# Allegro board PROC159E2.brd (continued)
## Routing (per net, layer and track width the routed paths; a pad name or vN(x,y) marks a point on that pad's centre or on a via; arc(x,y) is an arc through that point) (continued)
SOC_OSPI0_D1: length 17.1
  L03_SIG1 w0.091: v1(47.44,39.67) 47.44,40.01 47.18,40.27 46.82,40.27 46.03,39.48 45.92,39.48 45.84,39.56 45.84,39.67 46.23,40.07 46.23,40.18 46.15,40.26 46.04,40.26 45.64,39.87 45.53,39.87 45.45,39.95 45.45,40.06 45.85,40.46 45.85,40.57 45.77,40.65 45.65,40.65 45.26,40.26 45.14,40.26 45.06,40.34 45.06,40.45 45.46,40.85 45.46,40.99 45.38,41.07 44.97,41.07 44.89,41.16 44.89,41.27 44.97,41.35 45.38,41.35 45.57,41.54 45.57,42.21 45.22,42.55 45.22,43.14 44.97,43.39 44.24,43.39 v1(43.67,42.82)
  BOTTOM w0.147: R91.1 R122.1 47.8,38 48.01,38.22 48.01,39.09 v1(47.44,39.67) ; U80.4 v1(43.67,42.82)
SOC_OSPI0_D2: length 15.6
  L03_SIG1 w0.091: v1(48.51,40.83) 48.23,41.11 47.99,41.11 47.48,40.6 47.37,40.6 47.29,40.68 47.29,40.79 47.86,41.37 47.86,41.48 47.78,41.56 47.67,41.56 47.09,40.99 46.98,40.99 46.9,41.07 46.9,41.18 47.47,41.75 47.47,41.87 47.39,41.95 47.28,41.95 46.7,41.38 46.59,41.38 46.51,41.46 46.51,41.57 47.08,42.14 47.08,42.26 47,42.34 46.89,42.34 46.14,41.59 46.02,41.59 45.94,41.67 45.94,41.78 46.7,42.53 46.7,42.69 46.2,43.19 45.95,43.19 45.81,43.05 v1(45.81,42.8)
  BOTTOM w0.147: U80.5 45.33,42.32 v1(45.81,42.8) ; R92.1 v1(48.51,40.83)
SOC_OSPI0_D3: length 17.3
  L03_SIG1 w0.091: v1(43.67,41.82) 43.22,41.82 43.11,41.94 43.11,43.04 42.97,43.18 42.79,43.18 42.67,43.06 42.67,36.4 43.82,35.25 46.44,35.25 46.65,35.47 48.08,35.47 v1(48.51,35.04)
  BOTTOM w0.147: v1(48.51,35.04) 48.58,35.12 R93.1 ; U80.6 v1(43.67,41.82)
SOC_OSPI0_D4: length 10.8
  TOP w0.147: R94.1 48.88,39.08 47.16,39.08 46.9,38.82 46.9,38.27 46.77,38.14 46.59,38.14 46.46,38.27 46.46,39.18 46.33,39.31 46.15,39.31 46.02,39.18 46.02,38.14 45.89,38.01 45.71,38.01 45.58,38.14 45.58,38.91 45.34,39.14 45.15,39.14 v1(44.83,38.82)
  BOTTOM w0.147: v1(44.83,38.82) 44.33,39.32 U80.11
SOC_OSPI0_D5: length 8.8
  TOP w0.147: R95.1 48.91,41.39 47.64,41.39 47.52,41.26 47.52,40.86 47.39,40.73 47.2,40.73 47.07,40.86 47.07,41.26 46.94,41.39 46.22,41.39 v1(43.65,38.82)
  BOTTOM w0.147: U80.12 v1(43.65,38.82)
SOC_OSPI0_D6: length 10.1
  TOP w0.147: R96.1 48.91,40.25 46.71,40.25 46.58,40.12 46.58,39.82 46.45,39.7 46.26,39.7 46.13,39.82 46.13,40.12 46.01,40.25 45.61,40.25 44.32,38.95 44.32,38.34 v1(44.83,37.83)
  BOTTOM w0.147: U80.13 44.34,38.32 v1(44.83,37.83)
SOC_OSPI0_D7: length 10.1
  TOP w0.147: R97.1 48.91,42.53 46.88,42.53 43.89,39.54 43.58,39.54 43.2,39.16 43.2,38.29 v1(43.67,37.82)
  BOTTOM w0.147: U80.14 v1(43.67,37.82)
SOC_OSPI0_DQS: length 18.3
  L03_SIG1 w0.091: v1(48.51,38.54) 48.51,38.06 48.43,37.98 47.19,37.98 47.11,37.9 47.11,37.79 47.19,37.71 48.43,37.71 48.51,37.63 48.51,37.51 48.43,37.43 47.19,37.43 47.11,37.35 47.11,37.24 47.19,37.16 48.43,37.16 48.51,37.08 48.51,36.96 48.43,36.88 47.19,36.88 47.11,36.8 47.11,36.69 47.19,36.61 48.43,36.61 48.55,36.49 48.55,35.93 48.37,35.75 46.75,35.75 46.57,35.93 46.57,36.63 46.39,36.82 v1(44.67,36.82)
  BOTTOM w0.147: v1(44.67,36.82) 44.17,37.32 U80.15 ; R118.1 v1(48.51,38.54)
SOC_OSPI0_LBCLK: length 9.1
  L03_SIG1 w0.091: v1(43.67,36.82) 43.67,37.15 44,37.48 44.44,37.48 44.64,37.28 45.42,37.28 45.57,37.43 45.57,37.89 45.74,38.06 46.13,38.06 46.39,37.8 46.66,37.8 46.78,37.91 46.78,38.68 47.09,39 47.82,39 v1(48.51,39.69)
  BOTTOM w0.147: U80.16 v1(43.67,36.82) ; R117.1 v1(48.51,39.69)
SOC_SPI1_CLK: length 77.1
  TOP w0.147: R140.1 v1(60.2,51.73) ; v1(63.01,8.36) 62.55,8.36 61.91,9 R43.2 U8.4
  L08_SIG2 w0.091: v1(60.2,51.73) 61.86,53.39 63.67,53.39 64.94,52.12 66.63,52.12 67.17,51.58 67.17,51.06 67.85,50.38 68.6,50.38 69.6,49.38 71.12,49.38 72.47,48.02 72.47,47.2 75.67,44 75.67,43.11 76.17,42.62 76.17,38.95 76.89,38.22 76.89,35.56 77.97,34.49 77.97,31.17 78.43,30.71 78.43,30.12 80,28.54 80,28.04 80.42,27.62 80.42,26.66 78.79,25.03 78.79,20.85 78.37,20.44 78.37,18.83 74.31,14.76 69.14,14.76 66.75,12.37 66.75,10.07 66.64,9.97 63.82,7.15 62.86,7.15 62.61,7.4 62.61,7.95 v1(63.01,8.36)
SOC_SPI1_CS0: length 50.4
  TOP w0.147: v1(61.84,19.3) R46.2 U8.12
  L03_SIG1 w0.091: v1(59.37,52.7) 59.69,52.39 59.69,51.12 60.37,50.43 60.37,40.16 60.59,39.94 60.59,37.46 60.81,37.24 61.99,37.24 62.17,37.06 62.17,36.63 62.36,36.44 65.92,36.44 66.17,36.19 66.17,35.09 66.42,34.84 68.32,34.84 69.06,34.1 69.06,32.53 67.2,30.67 67.2,26.34 65.36,24.5 65.36,23.48 64.68,22.79 63.61,22.79 63.61,22.79 62.34,22.79 62.05,22.5 62.05,19.88 61.84,19.67 v1(61.84,19.3)
  BOTTOM w0.147: R144.1 60.21,50.88 59.69,51.4 59.69,52.38 v1(59.37,52.7)
SOC_SPI1_D0: length 59.5
  TOP w0.147: R44.2 65.95,12.07 66.51,12.63 v1(66.51,13.16) 64.18,13.16 63.86,12.85 U8.7
  L08_SIG2 w0.091: v1(66.51,13.16) 66.99,13.65 66.99,14.05 69.89,16.94 74.98,16.94 75.91,17.87 75.91,33.69 74.93,34.68 74.93,37.95 74.2,38.68 74.2,41.99 69.65,46.54 69.65,47.64 68.04,49.25 67.41,49.25 66.68,49.98 64.79,49.98 63.33,51.45 v1(63.33,52.31)
  BOTTOM w0.147: R141.1 62.73,50.88 63.33,51.49 v1(63.33,52.31)
SOC_SPI1_D1: length 37.7
  TOP w0.147: U1.D9 v1(59.38,44.83) ; U8.9 R45.2 v1(65.27,19.3)
  L08_SIG2 w0.091: v1(59.38,44.83) 59.64,44.57 59.64,44.53 59.79,44.39 59.79,40.43 60.15,40.07 60.15,40.07 60.6,39.62 67.54,39.62 67.78,39.38 67.78,32.52 67.15,31.89 67.15,26.84 66.42,26.11 66.42,23.72 64.73,22.03 64.73,19.85 v1(65.27,19.3)
SOC_TA_I2C2_SCL: length 35.8
  L03_SIG1 w0.091: v1(46.1,77.46) 46.94,78.3 46.94,93.13 50.29,96.49 61.06,96.49 v1(63.11,98.54)
  BOTTOM w0.147: R302.1 v1(63.11,98.54) ; R310.2 v1(46.1,77.46)
SOC_TA_I2C2_SDA: length 44.6
  L08_SIG2 w0.091: v1(65.15,98.54) 65.57,98.97 66.34,98.97 66.59,98.72 66.59,97.58 66.15,97.15 66.15,90.87 64.71,89.42 64.71,78.74 63.61,77.65 61.93,77.65 60.53,79.05 50.44,79.05 49.61,78.22 47.92,78.22 v1(45.97,76.26)
  BOTTOM w0.147: R311.2 v1(45.97,76.26) ; R304.1 v1(65.15,98.54)
SOC_TCK: length 36.1
  TOP w0.147: U1.B3 v1(54.58,46.43) ; U30.12 v1(36.06,61.09)
  L03_SIG1 w0.091: v1(54.58,46.43) 54.97,46.82 54.97,47.4 53.54,48.83 53.54,51.72 49.71,55.54 36.61,55.54 33.99,58.17 33.99,60.35 34.73,61.09 v1(36.06,61.09)
  BOTTOM w0.147: TP52.1 36.1,61.06 v1(36.06,61.09)
SOC_TDI: length 38.6
  TOP w0.147: v1(34.41,59.14) 33.76,59.79 U30.7 ; U1.C5 v1(56.18,45.63)
  L03_SIG1 w0.091: v1(56.18,45.63) 55.79,46.02 55.79,47.47 55.21,48.04 54.64,48.04 53.72,48.96 53.72,51.79 48.39,57.12 36.43,57.12 v1(34.41,59.14)
  BOTTOM w0.114: 56.58,47.49 56.58,46.03 v1(56.18,45.63)
  BOTTOM w0.147: 56.58,47.49 56.58,48.04 57.19,48.65 TP53.1
SOC_TDO: length 33.4
  TOP w0.147: U30.4 34.21,61.74 35.13,60.83 35.13,58.48 36.22,57.39 TP54.1 43.7,56.76 44.39,56.76 v1(45.09,56.05)
  L08_SIG2 w0.091: v1(45.09,56.05) 44.56,55.52 44.56,52.39 45,51.95 53.08,51.95 53.79,52.65 54.91,52.65 v1(55.37,52.2)
  BOTTOM w0.147: v1(55.37,52.2) R177.1
SOC_TDO_R: length 5.5
  TOP w0.147: U1.C4 v1(55.38,45.63)
  BOTTOM w0.114: 54.98,47.49 54.98,46.03
  BOTTOM w0.147: 54.98,46.03 v1(55.38,45.63) ; R177.2 55.37,49.69 54.98,49.31 54.98,47.49
SOC_TMS: length 33.1
  TOP w0.147: U1.D5 v1(56.18,44.83) ; v1(36.06,59.14) U30.9
  L03_SIG1 w0.091: v1(56.18,44.83) 56.57,45.22 56.57,47.39 55.66,48.3 54.64,48.3 53.91,49.04 53.91,51.87 48.3,57.47 37.73,57.47 v1(36.06,59.14)
  BOTTOM w0.147: v1(36.06,59.14) 36.18,59.02 TP55.1
SOC_XDS_I2C2_SCL: length 20.9
  TOP w0.147: R312.2 v1(39.03,78.27)
  L03_SIG1 w0.091: v1(27.68,88.72) 28.66,87.74 34.63,87.74 38.17,84.21 38.17,79.14 v1(39.03,78.27)
  BOTTOM w0.147: U52.82 27.94,88.46 v1(27.68,88.72)
SOC_XDS_I2C2_SDA: length 22.6
  TOP w0.147: R313.2 v1(39.11,76.06)
  L03_SIG1 w0.091: v1(39.11,76.06) 39.46,76.41 39.46,78.76 38.35,79.87 38.35,84.29 34.71,87.93 29.36,87.93 v1(28.57,88.72)
  BOTTOM w0.147: v1(28.57,88.72) 28.34,88.49 U52.81
SPI1_MUX_OE#: length 2
  TOP w0.147: U8.15 60.61,18.84 61.08,19.3 R50.1
SPI1_MUX_SEL: length 146.3
  TOP w0.147: v1(60.83,9.92) R49.1 U8.1
  L08_SIG2 w0.091: v1(57.88,65.65) 57.51,65.65 56.96,66.2 56.96,66.75 55.97,67.73 54.89,67.73 53.74,68.88 53.74,69.34 53,70.08 49.81,70.08 47.82,68.09 45.44,68.09 45.21,67.87 30.11,67.87 28.19,65.94 26.48,65.94 19.92,59.39 19.92,58.06 15.32,53.46 15.32,39.14 17.39,37.06 17.39,33.88 15.35,31.84 15.35,22.05 18.39,19.02 v1(23.79,19.02)
  BOTTOM w0.147: v1(57.88,65.65) 57.56,65.97 57.27,65.97 56.96,66.29 U60.11 ; v1(23.79,19.02) 24.11,19.34 24.51,19.34 24.52,19.34 25.68,20.51 35.52,20.51 36.85,21.83 49.55,21.83 52.82,18.56 56.48,18.56 60.07,14.98 60.07,10.68 v1(60.83,9.92)
SW_PB_INTN: length 12.2
  TOP w0.147: Q10.2 59.62,94.18 59.65,94.2 v1(59.65,95.49) SW11.2
  BOTTOM w0.147: U76.3 52.56,92.43 52.96,92.84 56.14,92.84 58.8,95.49 v1(59.65,95.49)
SW_PB_PORZ: length 5.9
  TOP w0.147: SW10.2 52.69,95.79 53.15,95.33 Q9.2 v1(53.15,92.38)
  BOTTOM w0.147: v1(53.15,92.38) 53.56,91.97 U76.1
SW_PB_RESETZ: length 28
  TOP w0.147: Q11.2 SW12.2 65.18,96.84 64.64,97.37 64.64,98.9 63.91,99.63 51.8,99.63 50.42,98.25 50.42,95.61 52.07,93.96 v1(52.07,93.33)
  BOTTOM w0.147: U76.6 52.56,93.82 v1(52.07,93.33)
SYS_BOOTMODE0: length 8.6
  TOP w0.147: R323.2 SW6.1 v1(62.86,84.71) 61.97,83.81 U47.2
  BOTTOM w0.147: U48.6 63.77,86.3 63.53,86.06 63.53,85.38 v1(62.86,84.71)
SYS_BOOTMODE1: length 9.3
  TOP w0.147: U47.3 61.47,84.57 v1(62.86,85.97) 63.17,85.97 63.18,85.98 SW6.2 R324.2
  BOTTOM w0.147: v1(62.86,85.97) 63.59,86.7 U48.7
SYS_BOOTMODE2: length 10.5
  TOP w0.147: U47.4 60.97,84.95 62.23,86.21 62.23,86.61 v1(62.86,87.25) SW6.3 R325.2
  BOTTOM w0.147: U48.8 63.46,87.1 63.31,87.25 v1(62.86,87.25)
SYS_BOOTMODE3: length 14.2
  TOP w0.147: U47.5 60.27,81.91 60.25,81.93 60.25,85.9 v1(62.86,88.52) SW6.4 R326.2
  BOTTOM w0.147: v1(62.86,88.52) 64.37,88.52 64.95,87.94 U48.9
SYSBOOT_BUF_ENZ: length 6.7
  BOTTOM w0.147: U49.2 67.93,96.48 67.44,96 66.04,96 64.8,94.77 R328.1
TA_GPIO1: length 33.2
  TOP w0.147: R371.2 v1(45.59,105.27) ; Q10.1 61.55,95.15 60.63,96.08 60.63,98.87 60.32,99.17 59.52,99.17 v1(58.84,98.49)
  L08_SIG2 w0.091: v1(58.84,98.49) 59.22,98.11 60.24,98.11 60.49,98.36 60.49,98.74 56.62,102.61 44.64,102.61 44.19,103.06 44.19,103.87 v1(45.59,105.27)
  BOTTOM w0.147: R298.1 v1(58.84,98.49) 58.84,97.89 58.92,97.81 R291.1
TA_GPIO1_XDS: length 22.4
  TOP w0.147: U57.2 R365.2 31.57,105.9 v1(31.56,105.9)
  L08_SIG2 w0.091: v1(31.14,88.72) 31.41,88.98 31.41,89.23 32.55,90.36 32.55,102.99 31.14,104.4 31.14,105.48 v1(31.56,105.9)
  BOTTOM w0.147: U52.74 v1(31.14,88.72)
TA_GPIO2: length 74.7
  L08_SIG2 w0.091: v1(60.07,98.54) 56.3,102.31 45.71,102.31 44.45,101.05 44.45,98.08 45.51,97.02 45.51,74.26 42.89,71.65 28.71,71.65 27.81,72.56 v1(19.81,72.56)
  BOTTOM w0.147: R290.1 v1(60.07,98.54) R299.1 ; R378.2 v1(19.81,72.56)
TA_GPIO2_XDS: length 19.5
  L08_SIG2 w0.091: v1(31.54,86.1) 31.54,85.52 27.55,81.52 18.3,81.52 v1(17.92,81.14)
  BOTTOM w0.147: U58.2 R377.2 v1(17.92,81.14) ; U52.73 v1(31.54,86.1)
TA_GPIO3: length 43.8
  TOP w0.147: R372.2 v1(45.59,104.13)
  L03_SIG1 w0.091: v1(61.08,98.54) 64.26,101.71 J12.1
  L08_SIG2 w0.091: J12.1 59.82,101.71 57.4,104.13 v1(45.59,104.13)
  BOTTOM w0.147: J12.1 68.14,101.71 67.3,100.87 67.3,98.46 66.98,98.14 U49.1 ; R300.1 v1(61.08,98.54) 61.08,97.93 61.21,97.81 R289.1
TA_GPIO3_XDS: length 20.7
  TOP w0.147: v1(31.57,104.57) R366.2 U57.3
  L08_SIG2 w0.091: v1(31.57,104.57) 33.02,103.12 33.02,90.06 v1(32.65,89.69)
  BOTTOM w0.147: U52.72 31.94,88.83 32.33,89.22 32.33,89.37 v1(32.65,89.69)
TA_GPIO4: length 39.2
  TOP w0.147: R373.2 v1(44.87,103.45) ; U47.1 v1(62.47,83.03)
  L08_SIG2 w0.091: v1(44.87,103.45) 56.72,103.45 60.97,99.2 61.44,99.2 v1(62.1,98.54) 62.9,97.74 62.9,91.3 62.08,90.48 62.08,83.42 v1(62.47,83.03)
  BOTTOM w0.147: R301.1 v1(62.1,98.54) 62.1,98.08 62.35,97.83 R288.1
TA_GPIO4_XDS: length 21
  TOP w0.147: v1(35.8,102.72) U57.4 R367.2
  L08_SIG2 w0.091: v1(32.69,88.69) 33.62,89.62 33.62,100.54 v1(35.8,102.72)
  BOTTOM w0.147: v1(32.69,88.69) 32.34,88.34 U52.71
TA_PORZN: length 21.9
  TOP w0.147: R374.2 v1(44.87,100.87) ; v1(56.88,98.54) 56.38,98.04 56.38,95.58 55.05,94.24 Q9.1
  L08_SIG2 w0.091: v1(44.87,100.87) 45.93,101.93 53.49,101.93 v1(56.88,98.54)
  BOTTOM w0.147: R293.1 56.64,97.84 56.88,98.08 v1(56.88,98.54) R296.1
TA_PORZN_XDS: length 19.9
  TOP w0.147: v1(31.57,100.86) R368.2 U57.5
  L08_SIG2 w0.091: v1(31.57,100.86) 30.84,100.14 30.84,91.5 29.12,89.78 29.12,86.94 v1(29.94,86.12)
  BOTTOM w0.147: U52.77 v1(29.94,86.12)
TA_POWERDOWNZ: length 161.5
  TOP w0.147: R376.2 v1(44.87,98.33)
  L03_SIG1 w0.091: v1(104.07,98.36) 104.07,104.16 100.32,107.92 81.42,107.92 75.41,101.9 71.28,101.9 70.36,102.83 68.27,102.83 67.49,102.05 59.38,102.05 v1(55.88,98.54)
  L08_SIG2 w0.091: v1(104.07,98.36) 104.07,97.45 105.48,96.05 105.48,83.57 100.76,78.86 97.87,78.86 96.7,77.68 92.49,77.68 92.09,78.07 90.97,78.07 90.47,77.57 90.47,76.51 94.56,72.41 94.56,66.27 95.32,65.51 95.32,40.69 93.89,39.26 93.89,38.13 94.2,37.83 95.19,37.83 v1(95.72,37.31) ; v1(55.88,98.54) 55.23,99.18 46.49,99.18 45.63,98.33 v1(44.87,98.33)
  BOTTOM w0.147: Q12.1 87.47,36.93 87.71,37.17 91.05,37.17 91.66,37.78 95.24,37.78 v1(95.72,37.31) ; R295.1 v1(55.88,98.54) 55.41,98.07 R468.1
TA_POWERDOWNZ_XDS: length 14.2
  TOP w0.147: U57.7 R370.2 v1(31.57,98.32)
  L08_SIG2 w0.091: v1(31.57,98.32) 31.57,90.74 v1(29.54,88.72)
  BOTTOM w0.147: U52.78 v1(29.54,88.72)
TA_RESETZ: length 33.9
  TOP w0.147: v1(57.85,98.54) 58.38,98.01 58.38,91.13 58.76,90.75 61.7,90.75 63.58,92.64 Q11.1 ; R375.2 v1(44.87,99.6)
  L08_SIG2 w0.091: v1(44.87,99.6) 45.58,100.31 54.71,100.31 56.3,98.72 56.3,98.52 56.71,98.11 57.42,98.11 v1(57.85,98.54)
  BOTTOM w0.147: R297.1 v1(57.85,98.54) 57.85,98.08 57.78,98.02 R292.1
TA_RESETZ_XDS: length 15.5
  TOP w0.147: v1(31.57,99.59) R369.2 U57.6
  L08_SIG2 w0.091: v1(31.57,99.59) 31.99,99.17 31.99,90.53 v1(31.11,89.65)
  BOTTOM w0.147: U52.76 30.34,88.88 v1(31.11,89.65)
TCAN_WAKE: length 7.3
  TOP w0.147: U29.9 v1(19.9,24.41)
  BOTTOM w0.147: v1(19.9,24.41) 19.9,18.48 R31.2
TM4C129_RST#: length 7.6
  BOTTOM w0.147: U52.70 32.74,86.2 32.51,85.97 TP73.1 33.9,83.55 34.16,83.3 R353.2 R355.1
TM4C129_TCK: length 3.1
  BOTTOM w0.147: U52.100 19.19,90.11 18.71,90.59 TP68.1
TM4C129_TDI: length 5.5
  BOTTOM w0.147: TP70.1 16.67,89.31 U52.98
TM4C129_TDO: length 3.1
  BOTTOM w0.147: U52.97 19.2,88.91 18.74,88.46 TP71.1
TM4C129_TMS: length 5.4
  BOTTOM w0.147: TP69.1 16.6,89.71 U52.99
TMP411_ALERT: length 1.7
  BOTTOM w0.147: R160.2 U27.6
TMP411_THERM: length 1.8
  BOTTOM w0.147: U27.4 R161.2
TPS2121_CP2: length 6.7
  TOP w0.147: U4.3 96.02,19.81 v1(95.52,20.31)
  BOTTOM w0.147: R11.2 R15.1 97.59,20.87 97.02,20.31 v1(95.52,20.31)
TPS2121_OV1: length 5.4
  TOP w0.147: U4.5 95.02,19.81 v1(94.52,20.31)
  BOTTOM w0.147: v1(94.52,20.31) 94.52,21.1 95.05,21.64 R12.2 R16.1
TPS2121_OV2: length 8.8
  TOP w0.147: U4.4 v1(95.52,19.29)
  BOTTOM w0.147: R14.1 R10.2 100.13,20.45 98.97,19.29 v1(95.52,19.29)
TPS2121_PR1: length 5.2
  TOP w0.147: U4.6 v1(94.52,19.29)
  BOTTOM w0.147: R17.1 R13.2 93.78,20.03 v1(94.52,19.29)
TPS2296_EN: length 8.5
  TOP w0.147: U2.4 LD1.1 103.78,15.39 103.44,15.74 v1(101.47,15.74) ; U3.3 v1(103.25,18.55)
  BOTTOM w0.147: v1(101.47,15.74) 102.11,16.38 102.11,17.42 v1(103.25,18.55)
TUSB_OUT1: length 3.2
  TOP w0.147: U2.2 103.28,11.6 v1(103.03,11.35)
  BOTTOM w0.147: U17.7 102,11.67 R4.2 v1(103.03,11.35)
TUSB_OUT2: length 5.5
  TOP w0.147: v1(100.2,11.35) 102,11.35 102.78,12.13 U2.1
  BOTTOM w0.147: U17.8 101.6,11.86 101.08,11.35 R3.2 v1(100.2,11.35)
UART0_RXD: length 57.5
  TOP w0.147: U1.A7 v1(57.78,47.23)
  L03_SIG1 w0.091: v1(50.9,94.09) 50.9,92.62 55.63,87.89 55.63,77.83 57.74,75.72 57.74,72.97 56.29,71.51 54.58,71.51 51.33,68.27 51.33,58.08 56.26,53.16 56.26,50.6 57.17,49.69 57.17,47.84 v1(57.78,47.23)
  BOTTOM w0.147: R344.1 v1(50.9,94.09)
UART0_TXD: length 59.4
  TOP w0.147: U1.A6 v1(56.98,47.23)
  L03_SIG1 w0.091: v1(56.98,47.23) 56.98,47.6 56.21,48.38 56.21,49.67 56.05,49.82 56.05,53 51,58.05 51,70.21 52.57,71.78 56.06,71.78 57.46,73.17 57.46,75.62 55.35,77.73 55.35,87.76 50.54,92.57 50.54,93.15 49.98,93.71 v1(49.4,93.71)
  BOTTOM w0.147: U54.3 v1(49.4,93.71)
UART2_MUX_SEL: length 12.7
  TOP w0.147: v1(56.46,66.54) 55.92,67.07 51.08,67.07 50.69,66.68 R62.2 R67.1 46.34,66.68 45.87,66.21 U20.1
  BOTTOM w0.147: U60.12 v1(56.46,66.54)
UART2_RXD_HSEC: length 110.9
  TOP w0.147: J15.161 104.84,4.21 105.18,4.56 v1(105.64,4.56) ; U20.3 47.75,64.31 49.11,62.95 v1(49.11,62.16)
  L08_SIG2 w0.091: v1(105.64,4.56) 106.38,3.82 108.84,3.82 109.36,4.33 109.36,7.96 107.69,9.63 105.52,9.63 105.13,10.02 103.6,10.02 102.33,11.29 102.33,11.73 98.57,15.5 96.51,15.5 95,17.01 95,20.68 86.66,29.02 86.24,29.02 85.46,29.8 85.46,39.91 82.56,42.81 82.56,45.24 80.41,47.4 80.41,51.17 77.79,53.79 71.71,53.79 71.1,54.4 69.44,54.4 68.98,54.86 68.98,55.21 68.47,55.73 67.26,55.73 66.09,56.9 52.92,56.9 49.11,60.71 v1(49.11,62.16)
UART2_TXD_HSEC: length 110.4
  TOP w0.147: v1(47.41,62.09) 47.15,62.36 U20.6
  L08_SIG2 w0.091: v1(104.04,5.58) 103.66,5.58 103.07,6.17 103.07,6.59 101.52,8.14 99.14,8.14 98.74,8.55 98.74,9.06 92.44,15.36 87.97,15.36 83.19,20.15 83.19,27.87 79.54,31.52 79.54,38.82 77.94,40.42 77.94,48.6 76.68,49.86 74.93,49.86 73.31,51.48 70.92,51.48 69.89,52.52 67.95,52.52 67.19,53.28 66.19,53.28 65.03,54.44 53.98,54.44 51.72,52.18 45.26,52.18 44.82,52.62 44.82,55.05 45.67,55.89 45.67,60.35 v1(47.41,62.09)
  BOTTOM w0.147: v1(104.04,5.58) 104.67,4.94 104.67,4.27 104.84,4.1 J15.162
USB_XDS110_ID: length 20.7
  TOP w0.147: v1(15.11,93.97) 14.74,94.33 J13.4
  L08_SIG2 w0.091: v1(15.11,93.97) 22.47,86.6 v1(22.47,83.05)
  BOTTOM w0.147: R338.2 v1(22.47,83.05) ; U53.4 13.16,93.38 13.33,93.21 14.73,93.21 15.11,93.59 v1(15.11,93.97)
USD_LS_EN: length 2
  TOP w0.147: U23.3 14.06,53.84 14.06,53.84 U22.4
USER_LED0: length 10.5
  TOP w0.147: U20.5 47.35,63.01 48.01,62.35 48.01,61.58 49.81,59.79 53.55,59.79 53.88,59.46 R146.2
USER_LED1: length 19.2
  TOP w0.147: R147.2 47.93,55.15 46.07,53.29 46.07,52.7 44.02,50.65 44.02,45.75 45.97,43.8 49.04,43.8 R194.2
VLIN: length 9.6
  TOP w0.381: J10.1 D6.2 ; D6.2 C236.1 SW4.2 ; D6.2 U45.7
VMAIN: length 23.4
  TOP w0.381: TP80.1 97.66,88.45 v1(98.18,88.97) ; C12.2 97.34,16.94 U4.1 ; R137.1 58.64,63.47 57.73,62.56 57.73,57.8 57.19,57.27 R138.1 ; R433.1 v1(79.2,28.28)
  BOTTOM w0.254: U14.7 99.31,87.21 98.69,87.83
  BOTTOM w0.305: 53.94,79.39 53.94,79.21 53.58,78.85 ; 53.94,79.39 U10.2 ; 53.94,79.39 54.37,78.96
  BOTTOM w0.381: v1(53.97,28.18) 53.97,28.75 54.34,29.13 R201.1 ; U5.8 87.98,15.61 88.21,15.84 v1(90.42,15.84)
  vias: v1(53.97,77.58) v1(54.86,77.58) v1(90.42,17.77) v1(90.42,16.8) v1(91.44,17.77) v1(91.44,16.8)
VMAIN_12V0: length 10.3
  TOP w0.305: U29.10 18.03,23.91 17.69,24.25 C348.2
  TOP w0.381: C348.2 v1(17.07,23.54)
  BOTTOM w0.381: R21.2 C20.1 76.74,19.11 v1(76.85,19.22) ; v1(17.07,23.54) 17.07,21.21 16.85,20.99 R175.1
  vias: v1(93.39,28.66) v1(94.14,27.91)
VMAIN_MON: length 3
  TOP w0.381: U79.2 81.18,29.94 81.15,29.97 R434.1 R433.2
VMAINP_12V0:
  vias: v1(97.4,32.25) v1(97.4,31.36) v1(97.4,30.47) v1(98.42,32.25) v1(98.42,31.36) v1(98.42,30.47) v1(99.31,33.13) v1(99.31,32.25) v1(99.31,31.36) v1(99.31,30.47)
VPP_1V7: length 55.8
  TOP w0.381: R463.1 85.77,45.17 C346.1 84.59,46.22 TP76.1 ; R83.1 49.12,35.69 47.83,35.69 47.82,35.68 R63.1 47.69,35.11 v1(47.62,35.04)
  L05_PWR1 w0.305: v1(47.62,35.04) 48,34.66 48,34.26 50.46,31.8 67.63,31.8 68.71,30.71 71.56,30.71 72.2,31.36 78.16,31.36 84.64,37.84 84.64,44.61 TP76.1
VPP_LDO_EN: length 72.1
  TOP w0.147: v1(86.31,59.6) 84.99,59.6 84.42,59.03 84.42,59.03 84.42,54.45 80.46,50.49 80.46,46 82.64,43.82 83.73,43.82 85.09,42.46 90.14,42.46 91.47,43.79 R465.1 90.91,44.85 90.84,44.92 U66.4 ; v1(61.61,63.44) 62.52,64.36 62.52,66.52 63.28,67.28 74.34,67.28 74.84,66.78 74.84,66.32 75.36,65.8 78.32,65.8 80.84,63.28 v1(80.84,61.89)
  L08_SIG2 w0.091: v1(80.84,61.89) 84.02,61.89 v1(86.31,59.6)
  BOTTOM w0.147: v1(61.61,63.44) 60.65,64.4 57.66,64.4 55.96,66.1 U60.13
VPP_R: length 3.5
  TOP w0.305: U1.N3 v1(54.58,36.83)
  TOP w0.381: v1(51.32,36.67) 51.05,36.4 C101.1 50.39,35.98 R83.2 50.03,35.62 R467.2
VREG: length 2.1
  TOP w0.305: v1(101.7,46.03) 101.69,46.02 U7.40
  BOTTOM w0.381: C62.1 101.7,45.45 v1(101.7,46.03)
VREG_1P8_OUT: length 3.9
  TOP w0.305: U7.39 102.19,45.77 102.24,45.81 102.24,46.19 102.23,46.2 v1(102.23,46.73)
  BOTTOM w0.381: C61.1 103.19,45.15 102.36,45.97 102.36,46.53 102.32,46.57 102.32,46.64 v1(102.23,46.73)
VSYS_1V2: length 17.4
  TOP w0.254: 90.29,55.99 90.59,56.3 U9.3 90.58,56.75 90.55,56.72 90.13,56.72 89.78,56.38
  TOP w0.381: R52.1 90.58,61.08 v1(90.58,61.48) 91.72,62.62 TP82.1
  L06_PWR2 w0.305: v1(85.09,53.2) 85.59,53.71 87.67,53.71 90.58,56.62 v1(90.58,61.48)
  BOTTOM w0.381: R75.3 84.2,50.63 v1(84.2,51.42)
  vias: v1(83.31,52.31) v1(83.31,51.42) v1(84.2,53.2) v1(84.2,52.31) v1(85.09,54.09) v1(85.09,52.31) v1(85.09,51.42) v1(85.97,54.09) v1(85.97,53.2) v1(85.97,52.31)
VSYS_1V2_EN: length 4.8
  TOP w0.147: v1(93.14,56.3) 93.14,56.75 92.64,57.25 U9.5
  BOTTOM w0.147: v1(93.14,56.3) 93.14,55.36 92.99,55.21 R430.2 R51.2
VSYS_1V2_FB: length 2.8
  TOP w0.203: R56.2 R52.2 90.27,59.2 90.33,59.13 U9.9
VSYS_1V2_PG: length 98.8
  TOP w0.147: R76.2 58.71,77.13 67.1,77.13 v1(67.43,77.46) ; U9.1 89.82,57.75 89.63,57.94 89.63,59.21 89.06,59.78 R59.2 88.41,59.78 88.11,60.08 v1(88.11,61.41) 87.43,62.09 87.02,62.09 84.09,59.17 84.09,54.54 79.78,50.22 79.78,46.26 82.54,43.5 83.48,43.5 84.04,42.94 84.04,38.82 80.19,34.98 U78.1
  L08_SIG2 w0.091: v1(88.11,61.41) 88.11,59.42 86.43,57.73 79.14,57.73 77.44,56.04 72.21,56.04 71.72,55.55 71.16,55.55 70.58,56.13 70.58,56.47 69.71,57.34 67.48,57.34 67.1,57.72 67.1,68.4 67.28,68.58 67.28,76.94 67.43,77.09 v1(67.43,77.46)
VSYS_1V2_SW: length 1.7
  TOP w0.254: 89.04,57.25 U9.2
  TOP w0.381: 88.77,57.52 89.04,57.25
VSYS_1V7_FB: length 2.8
  TOP w0.147: R464.1 R463.2 86.99,44.96 87.6,45.57 U66.2
VSYS_3V3_LDO1: length 280.6
  TOP w0.203: U87.30 73.52,60.39 v1(73.02,59.89)
  TOP w0.254: 103,50.87 v1(103,51.79)
  TOP w0.305: v1(79.01,55.89) 79.01,56.09 78.71,56.39 U87.1 ; 102.87,47.61 102.87,46.6 ; 102.87,46.6 103.19,46.27 U7.37 ; 102.87,46.6 102.87,46.47 102.69,46.3 U7.38 ; U84.30 v1(89.06,88.85) ; v1(23.84,24.75) C175.2 23.2,23.99 23.12,23.91 U29.5 ; U85.17 93.83,105.84 94.14,106.14 v1(94.14,106.34) ; R1647.1 v1(25.55,25.62) ; U85.1 v1(94.14,97.84) ; U84.17 93.83,92.85 94.14,93.15 v1(94.14,93.35) ; v1(94.14,84.34) 94.14,84.59 93.88,84.85 U84.1 ; v1(79.01,64.39) U87.17 ; U85.30 v1(89.06,101.84)
  TOP w0.381: R153.1 v1(56.7,51.73) ; R153.1 R152.1 57.84,54.4 59.03,55.59 R3842.1 v1(59.83,56.45) ; R153.1 R157.1 R156.1 ; U42.4 v1(19.41,39.48) ; U42.1 18.98,42.52 C233.1 18.98,44.6 18.92,44.66 FL6.1 C230.1 v1(15.74,45.9) ; R46.1 v1(62.56,21.07) ; R425.1 v1(51.83,107.41) ; J15.119 67.84,4.79 67.18,5.45 67.18,8.12 65.95,9.34 v1(65.95,10.4) 65.91,10.45 R44.1 ; v1(81.3,106.34) 81.8,105.84 C373.1 ; R3852.2 v1(96.56,101.34) ; R1678.2 R1679.2 42.45,37.2 42.65,36.99 C3743.1 42.65,35.69 v1(42.68,35.66) ; v1(49.92,97.02) 49.92,95.92 48.29,94.29 R3858.1 ; R470.1 74.97,28.4 v1(74.45,27.88) ; R80.1 R78.2 99.21,82.43 96.53,79.75 v1(95.53,79.75) ; R45.1 v1(65.27,20.28) ; v1(96.23,87.51) 95.86,87.88 R3849.2 ; v1(52.76,66.55) 53.35,65.97 C86.1 U20.16 ; C178.1 v1(41.72,63.56) ; U19.E4 v1(30.35,45.16) ; v1(87.29,88.35) 86.63,89.01 C371.1 ; R59.1 89.02,61.41 v1(88.98,61.45) ; R108.2 v1(25.81,40.66) ; R263.2 v1(69.77,94.3) ; R429.1 v1(65.8,107.41) ; R200.1 94.07,42.89 v1(94.32,43.14) ; R85.1 26.58,54.75 v1(26.58,54.75) ; v1(43.81,55.99) R84.1 R1668.2 ; v1(77.52,34.22) 77.75,33.99 R3832.1 ; 103.37,54.85 107.82,54.85 108.89,55.92 109.79,55.92 v1(110.61,55.11) 110.72,55 R40.1 ; v1(50.02,67.5) 48.38,67.5 R62.1 ; v1(43.68,44.82) 43.54,44.68 C3744.1 ; U36.5 C189.1 ; C189.1 v1(80.63,42.81) ; C189.1 77.34,42.81 v1(76.4,43.76) ; U19.B4 v1(30.35,41.16) ; v1(66.18,64.39) 66.55,64.77 C361.1 ; v1(28.11,62.43) R180.1 R181.1 ; v1(87.29,101.34) 86.67,101.96 C374.1 ; v1(59.12,19.3) C73.1 59.96,19.16 U8.16 ; R1667.2 v1(26.81,58.43) ; v1(103.12,56.63) 103.43,56.32 R48.1 ; R184.1 v1(40.29,67.08) ; U46.1 C240.1 v1(49.42,74.17) ; v1(31.23,49.51) C157.1 31.23,51.08 31.25,51.1 U18.8 ; v1(82.51,83.67) 82.86,84.02 C369.1 ; U78.5 83.31,33.37 84.05,34.11 C340.1 R431.1 v1(84.89,35.37) ; U79.5 C341.1 v1(84.79,33.35) ; R3872.1 v1(49.98,92.86) ; R426.1 v1(58.81,107.41) ; C370.1 v1(81.3,92.85) ; R183.1 R182.1 v1(42.41,58.95) ; R466.1 v1(17.8,20.65) ; R86.1 v1(41.65,51.93) ; C362.1 v1(71.25,60.39) ; R109.1 v1(37.08,41.1) ; v1(23.89,41.5) R102.1 R104.2 R103.2 ; v1(40.25,63.69) C177.1 U30.16 ; R43.1 v1(62.89,10.66) ; R276.2 v1(16.23,36.18) ; v1(38.4,40.32) 38.49,40.23 C3745.1 ; C360.1 v1(66.18,55.89) ; C372.1 v1(81.3,97.84) ; R471.1 v1(73.43,27.88) ; R267.2 v1(68.59,90.14) ; U19.D1 v1(34.54,43.66) ; R217.2 v1(80.79,36.44)
  L05_PWR1 w0.381: 94.95,87.92 95.82,87.92 v1(96.23,87.51) ; v1(90.07,78.07) 90.07,79.83
  BOTTOM w0.203: C243.1 65.75,84.2 U48.2
  BOTTOM w0.254: U80.17 v1(42.68,35.66) ; v1(80.63,42.81) 79.88,42.07 C3746.1 79.13,42.07 78.4,41.33 U90.10 ; C278.1 54.69,74.21 v1(55.46,73.44) U60.27 ; C335.1 54.67,94.4 U76.8 ; U80.30 v1(38.4,40.32) ; U81.10 C356.1 v1(71.03,31.36) ; U82.30 v1(71.25,60.39) ; U80.1 43.18,44.32 v1(43.68,44.82) ; C277.1 58.06,74.57 57.59,74.1 57.59,73.27 57.46,73.14 U60.31
  BOTTOM w0.305: v1(81.3,106.34) 81.8,105.84 C373.1 ; U88.30 86.11,101.84 86.24,101.96 86.67,101.96 v1(87.29,101.34) ; v1(82.51,83.67) 82.51,84.15 82.14,84.52 U89.1 ; C370.1 v1(81.3,92.85) ; C372.1 v1(81.3,97.84) ; v1(66.18,55.89) 66.18,56.09 66.48,56.39 U82.1 ; U89.30 86.07,88.85 86.18,88.96 86.68,88.96 v1(87.29,88.35) ; U82.17 v1(66.18,64.39)
  BOTTOM w0.381: C161.1 34.46,43.58 v1(34.54,43.66) 35.11,43.66 35.15,43.62 R101.2 R107.2 ; R111.2 30.92,41.73 v1(30.35,41.16) 30.87,40.63 C162.1 C164.2 ; v1(34.79,47.61) 34.78,47.63 R106.2 R100.2 R105.2 ; R430.1 92.99,52.76 v1(93,52.75) ; U39.5 C222.1 ; C222.1 78.28,99.37 79.02,100.11 R3861.1 ; C222.1 77.26,99.98 v1(77.52,100.25) ; R474.2 v1(75.16,30.61) ; v1(79.01,64.39) 78.79,64.62 C358.1 ; v1(80.79,36.44) 82.75,38.4 82.75,41.59 81.52,42.81 v1(80.63,42.81) ; R38.1 110.33,54.82 v1(110.61,55.11) ; C357.1 78.92,55.98 v1(79.01,55.89) ; C335.1 56.11,94.58 v1(56.13,94.6) ; R167.1 111.33,95.9 v1(110.98,96.25) ; v1(94.14,93.35) 93.5,93.99 C367.1 ; v1(64.5,60.62) 64.76,60.87 R3843.2 ; v1(77.8,30.72) 78.2,30.32 R472.1 ; R265.2 72.38,98.39 73.1,97.67 73.1,97.28 v1(73.51,96.87) 73.07,96.43 R155.1 R154.1 ; R214.1 v1(90.07,78.07) ; v1(89.06,88.85) 89.85,88.85 C368.1 ; U21.5 C166.1 35.74,36.5 R121.2 v1(36.44,36.56) ; U16.1 93.39,82.61 93.65,82.86 C98.1 v1(95.34,82.86) ; C160.1 C163.1 30.41,45.22 v1(30.35,45.16) ; C243.1 v1(66.92,83.79) ; v1(94.14,106.34) 93.89,106.09 C364.1 ; C359.1 73.77,60.64 v1(73.02,59.89) ; R436.1 v1(75.39,33.45) 76.74,33.45 R3867.1 ; 67.24,11.69 FL7.1 v1(67.24,17.77) ; C187.2 22.48,30.21 J6.10 ; v1(49.51,85.6) C181.2 U31.8 ; C363.1 93.81,97.51 v1(94.14,97.84) ; v1(31.23,49.51) C158.1 31.44,50.52 C159.2 ; v1(49.92,97.02) C265.1 U54.1 ; v1(32.91,72.14) C179.2 32.93,72.92 U32.1 ; C366.1 94.14,85.05 v1(94.14,84.34) ; v1(112.6,91.12) U28.8 C173.1 ; R392.2 v1(52.15,76.16) ; R427.1 v1(51.92,98.22) ; C365.1 89.85,101.84 v1(89.06,101.84) ; R1381.2 v1(80.11,60.83) ; R3866.1 v1(76.4,43.76) ; v1(108.99,47.1) 108.99,47.29 108.42,47.87 R41.1 ; v1(39.86,72.87) C171.1 40.53,72.25 40.57,72.21 U26.16 ; R3864.2 79.58,88.37 79.98,87.96 v1(80.37,87.96) ; R437.1 71.95,32.65 v1(71.76,32.45) ; C277.1 58.51,75.21 58.67,75.05 R395.2 v1(59.29,75.81) ; R428.1 v1(55.11,89.94) ; R120.2 v1(30.32,37.12) ; R162.1 R159.1 R158.1 v1(50.02,67.5) ; R473.1 v1(68.46,27.49)
  vias: v1(102.99,48.63)
VSYS_3V3_LDO2: length 104.5
  TOP w0.305: C66.1 103.24,35.39 102.74,35.89 102.74,36.24 102.69,36.29 U7.11
  TOP w0.381: R131.1 R130.1 R129.1 v1(23.49,48.76) ; 12.06,57.28 12.14,57.2 U23.1 ; 12.06,57.28 v1(12.06,58.53) ; 12.06,57.28 12.21,57.28 13.06,58.13 v1(13.06,58.52) ; R128.1 28.44,48.03 v1(28.44,48.88) ; R127.1 27.7,49.96 R132.1 27.7,51.88 v1(27.39,52.18) ; R125.2 v1(19.68,52.57) ; v1(103.98,34.53) 103.98,31.2 TP10.1 ; v1(26.03,66.41) 26.17,66.27 R285.2 R282.1 ; U22.5 C167.1 v1(12.31,50.66) R3835.1
  L03_SIG1 w0.381: 104.88,36.44 105.85,37.41 108.5,37.41 110.42,39.33 110.42,51.8 111.68,53.05 111.68,53.72 111.05,54.35 109.02,54.35 108.46,54.92 103.71,54.92 99.6,59.03 99.6,59.67 v1(98.93,60.34)
  L06_PWR2 w0.381: v1(98.93,60.34) 98.36,60.34 91.69,53.67 v1(91.69,52.95)
  BOTTOM w0.203: U12.6 96.96,59.62 97.68,60.34 C90.1 v1(98.93,60.34) ; U13.2 87.59,60.29 v1(87.26,60.63)
  BOTTOM w0.254: U13.2 87.59,57.42 89.09,55.92 U13.6 89.09,54.03 89.29,53.84 89.97,53.84 90.17,53.64 90.18,53.63 C89.1
  BOTTOM w0.305: U24.10 v1(28.44,48.88)
  BOTTOM w0.381: R160.1 v1(53.03,62.25) ; R277.1 25.94,66.5 v1(26.03,66.41) ; U33.16 35.64,28.57 35.65,28.56 C188.1 v1(36.34,27.67) ; U27.1 C172.2 v1(44.3,60.69) ; v1(36.55,66.47) C234.1 36.46,67.18 36.46,67.19 35.57,67.19 35.56,67.18 U44.16 ; U59.1 C276.1 v1(71.62,76.41) ; C89.1 v1(91.69,52.95) ; R133.1 v1(28.57,56.48) ; R124.2 v1(43.12,49.22) ; R204.1 v1(26.54,30.34) ; v1(43.26,64.5) R161.1
  vias: v1(103.81,35.14)
VSYS_MON: length 5.4
  TOP w0.381: U1.U2 v1(53.78,33.63)
  BOTTOM w0.381: v1(53.78,33.63) 53.96,33.63 54.34,33.25 C186.2 54.4,32.92 54.4,32.09 R203.1 54.35,31.02 R201.2 53.61,31.02 TP57.1
VSYS_TA_3V3: length 52
  TOP w0.203: U47.14 64.36,80.48 R321.2 64.45,80.98 U47.15
  TOP w0.381: v1(58.67,84.82) 58.67,83.22 TP21.1 ; R320.2 v1(60.19,77.71) ; C244.1 64.66,80.78 R321.2 ; C244.1 v1(65.78,80) 65.7,79.91 R287.1 65.7,78.64 64.77,77.71 R286.1 ; C244.1 v1(66.54,80.78) ; R316.1 R317.1 R318.1 R319.1 v1(52.95,88.52) ; U57.16 44.16,106.53 C351.2 v1(44.26,107.12) ; R73.1 R72.1 v1(50.09,78.09)
  BOTTOM w0.203: U10.8 53.44,82.82 53.22,83.05 v1(53.21,83.05) ; C242.1 65.02,84.46 65.35,84.8 U48.3
  BOTTOM w0.305: L5.2 56.66,85.1 54.44,82.88 U10.10
  BOTTOM w0.381: R468.2 56.64,96.27 R293.2 R292.2 ; R307.2 46.47,74.94 C241.1 46.48,74.9 v1(46.48,74.03) ; v1(65.68,93.19) C246.2 66.98,93.37 U49.5 ; C242.1 v1(64.28,83.79) ; R58.2 v1(50.92,84.19) ; v1(17.24,71.87) C275.1 17.24,73.13 17.24,73.13 U58.8 ; v1(49.5,80.61) C272.2 49.47,79.97 U56.8 ; R292.2 R291.2 R290.2 R289.2 R288.2 ; R292.2 v1(57.78,95.36) ; R322.2 v1(63.37,82.16) ; C238.1 v1(45.94,97.96) ; C239.1 v1(45.91,99.21) ; v1(63.77,90.68) C245.2 63.67,91.53 U50.5
  vias: v1(59.69,85.33) v1(60.7,85.33)
VSYS_TA_3V3_EN: length 2.8
  BOTTOM w0.147: U10.3 53.44,79.43 53.27,79.26 52.2,79.26 52.06,79.11 R57.2
VSYS_TA_3V3_PG: length 1.8
  BOTTOM w0.203: U10.7 52.94,82.55 51.97,83.52 R58.1
VSYS_TA_3V3_SW: length 1.5
  BOTTOM w0.305: U10.9 53.94,83.33 53.72,83.55
WARMRESETN: length 110.2
  TOP w0.305: U1.C3 v1(54.58,45.63)
  TOP w0.381: v1(22.98,54.6) 22.03,54.6 21.23,53.8 21.23,52.21 20.31,51.3 R126.1
  L03_SIG1 w0.091: v1(52.98,50.58) 52.22,51.35 52.22,52.78 49.64,55.36 35.27,55.36 31.67,58.96 29.37,58.96 25,54.6 v1(22.98,54.6)
  L08_SIG2 w0.091: v1(22.98,54.6) 22.06,55.52 22.06,60.17 26.92,65.03 38.79,65.03 39.56,65.8 40.93,65.8 41.51,66.39 50.59,66.39 52.18,64.8 58.01,64.8 59.46,66.24 59.46,67.76 58.3,68.93 58.3,73.87 v1(55.96,76.21)
  BOTTOM w0.114: 54.18,47.51 54.18,46.03
  BOTTOM w0.147: 54.18,47.51 54.18,47.83 53.91,48.1 R185.2 53.21,50.05 52.98,50.28 v1(52.98,50.58) 52.52,50.58 52.34,50.77 TP58.1 ; R394.1 v1(55.96,76.21) ; 54.18,46.03 v1(54.58,45.63)
WARMRESETN_R: length 1.5
  TOP w0.381: U22.1 18.05,51.36 R126.2
XDS110_EMU0: length 2.7
  BOTTOM w0.147: R357.2 38.07,98.32 37.46,97.71 U52.42
XDS110_EMU1: length 2.5
  BOTTOM w0.147: R356.2 38.13,97.09 37.91,97.31 U52.43
XDS110_PROG_STAZ1: length 2.2
  TOP w0.147: v1(23.54,101.46) 23.54,100.73 R342.2
  BOTTOM w0.147: U52.4 v1(23.54,101.46)
XDS110_PROG_STAZ2: length 2.3
  TOP w0.147: R343.1 23.09,104.04 v1(23.14,104.09)
  BOTTOM w0.147: U52.3 v1(23.14,104.09)
XDS110_TCK: length 22.2
  L08_SIG2 w0.091: v1(43.81,88.95) 44.24,88.52 44.24,87.5 43.99,87.25 42.85,87.25 40.68,89.42 40.67,89.42 37.62,92.48 37.62,97.81 v1(34.92,100.51)
  BOTTOM w0.147: U52.35 v1(34.92,100.51) ; U31.3 v1(43.81,88.95)
XDS110_TCK_ISO: length 37.4
  TOP w0.147: v1(38.79,61.77) 38.76,61.74 U30.13
  L03_SIG1 w0.091: v1(51.18,88.95) 48,85.77 48,65.8 44.23,62.03 39.05,62.03 v1(38.79,61.77)
  BOTTOM w0.147: R198.1 v1(51.18,88.95)
XDS110_TDI: length 30.5
  L08_SIG2 w0.091: v1(37.46,99.31) 35.83,100.94 34.74,100.94 33.99,100.18 33.99,88.51 34.69,87.8 34.69,81.42 v1(31.66,78.39)
  BOTTOM w0.147: U52.38 v1(37.46,99.31) ; U32.7 v1(31.66,78.39)
XDS110_TDI_ISO: length 15.3
  TOP w0.147: U30.6 v1(33.27,60.44)
  BOTTOM w0.147: R199.1 30.72,72.3 33.27,69.75 33.27,63.04 33.72,62.58 33.72,60.9 v1(33.27,60.44)
XDS110_TDO: length 27.9
  L08_SIG2 w0.091: v1(30.39,78.39) 30.81,77.96 31.83,77.96 34.88,81 34.88,90.76 34.37,91.27 34.37,99.16 v1(34.92,99.71)
  BOTTOM w0.147: U32.6 v1(30.39,78.39) ; U52.37 v1(34.92,99.71)
XDS110_TDO_ISO: length 15
  TOP w0.147: U30.3 v1(33.27,62.39)
  BOTTOM w0.147: U32.3 30.39,73.97 29.93,73.51 29.93,72.37 32.89,69.41 32.89,62.77 v1(33.27,62.39)
XDS110_TMS: length 18
  L08_SIG2 w0.091: v1(43.81,87.68) 40.57,90.92 39.76,90.92 38.1,92.58 38.1,99.48 v1(37.46,100.11)
  BOTTOM w0.147: U52.36 v1(37.46,100.11) ; U31.2 v1(43.81,87.68)
XDS110_TMS_ISO: length 41.5
  TOP w0.147: U30.10 v1(38.85,59.79)
  L03_SIG1 w0.091: v1(51.18,87.68) 50.38,87.68 48.27,85.57 48.27,65.45 45.97,63.14 45.97,59.85 43.97,57.85 40.41,57.85 38.85,59.42 v1(38.85,59.79)
  BOTTOM w0.147: v1(51.18,87.68) 50.99,87.68 50.99,87.68 R197.1
XDS110_TRST#: length 3.2
  BOTTOM w0.147: R337.1 38.1,99.56 37.97,99.43 37.97,98.8 37.67,98.51 U52.40
XDS110_UART0_RXD: length 13.2
  L08_SIG2 w0.091: v1(37.47,101.32) 39.34,99.45 39.34,97.52 43.14,93.71 v1(43.81,93.71)
  BOTTOM w0.147: U54.6 v1(43.81,93.71) ; U52.33 37.45,101.31 37.46,101.32 v1(37.47,101.32)
XDS110_UART0_TXD: length 11.5
  L08_SIG2 w0.091: v1(39.67,101.67) 39.67,97.61 42.29,94.98 v1(43.81,94.98)
  BOTTOM w0.147: U54.7 v1(43.81,94.98) ; R336.1 v1(39.67,101.67)
XDS110_VBUS_DET: length 3.3
  BOTTOM w0.147: R341.1 R340.2 U52.1
XDS_GND: length 68
  TOP w0.381: C273.1 v1(30.49,106.68) 30.48,106.67 ; v1(34.41,88.76) 34.52,88.65 C262.2 ; v1(25.06,91.6) C260.2 C259.2 ; C249.2 v1(20.95,101.84) ; v1(27.17,99.37) C268.2 C267.2 26.84,97.75 U55.1 ; R333.2 v1(17.17,105.68) ; v1(39.65,80.51) 39.75,80.41 39.75,79.46 R315.2 39.78,79.3 C352.2 ; LD9.1 v1(23.49,97.27) ; LD10.1 v1(23.11,105.39) ; J13.5 v1(14.19,93.68) ; U51.6 v1(18.35,103.83)
  BOTTOM w0.203: U52.48 37.26,95.31 37.7,94.87 C253.2 ; U52.64 34.56,88.91 v1(34.41,88.76) 34.34,88.69 U52.66 34.34,86.25 34.27,86.17 C255.2 ; C254.2 19.25,95.73 19.27,95.71 U52.114 ; C250.2 28.97,104.27 28.74,104.05 U52.17 ; U52.55 v1(34.93,92.51) ; U52.58 v1(34.93,91.31) ; U52.10 25.94,104.12 25.76,104.31 C251.2 ; C252.2 28.21,85.98 28.74,86.52 U52.80
  BOTTOM w0.305: v1(14.19,93.68) 14.19,94.18 U53.3
  BOTTOM w0.381: U31.4 v1(43.81,90.22) ; C269.1 v1(26.75,86.18) ; Y2.2 v1(24.42,80.8) ; v1(40.89,84.7) C182.1 40.87,85.41 R351.1 R350.1 ; C257.2 v1(38.98,92.84) ; R355.2 v1(36.17,81.67) ; C251.2 v1(25.76,105.88) ; C270.1 v1(23.77,86.18) ; v1(40.51,90.19) R349.1 R358.2 ; v1(39.65,80.51) 39.84,80.32 39.84,80.24 39.85,80.23 C271.1 ; v1(29.12,81.65) U32.5 ; R341.2 v1(21.36,107.01) ; C258.2 v1(34.92,104.89) ; R352.1 v1(36.12,83.62) ; C180.1 v1(31.11,81.65) ; C250.2 v1(28.97,105.91) ; C261.2 v1(18.33,97.6) ; C266.2 v1(40.13,95.26) ; U54.5 v1(43.81,92.44) ; C264.2 v1(21.2,83.02) ; R337.2 v1(40.25,99.56) ; Y2.4 v1(28.19,83.59) ; U58.4 v1(21.05,80.92) ; C253.2 v1(38.98,94.87) ; C274.2 v1(17.21,82.41) ; C252.2 v1(28.21,84.57) ; C254.2 v1(17.65,95.73) ; C255.2 v1(34.27,84.59) ; U58.3 v1(19.78,80.92) ; U56.4 v1(40.89,83.78)
  vias: v1(13.58,87.11) v1(13.58,85.97) v1(15.11,101.78) v1(17.01,101.97) v1(17.01,100.95) v1(18.03,101.97) v1(18.03,100.95) v1(19.05,101.97) v1(19.05,100.95) v1(22.22,80.12) v1(22.22,78.85) v1(27.05,80.12) v1(27.05,78.98)
XDS_RBIAS: length 2.6
  BOTTOM w0.147: U52.59 37.28,90.91 37.75,91.38 R358.1
XDS_USB_D_N: length 19.3
  TOP w0.107: v1(14.98,95.75) 14.75,95.51 14.17,95.51 14.05,95.63 J13.2
  L08_SIG2 w0.094: v1(23.74,89.14) 23.58,89.31 23.58,92.13 19.1,96.61 16.94,96.61 15.94,95.6 15.13,95.6 v1(14.98,95.75)
  BOTTOM w0.107: v1(14.98,95.75) 14.71,95.48 14.29,95.48 14.16,95.61 U53.1 ; U52.93 23.54,88.4 23.51,88.43 23.51,88.91 v1(23.74,89.14)
XDS_USB_D_P: length 19.2
  TOP w0.107: J13.3 13.95,94.98 14.26,95.3 14.67,95.3 v1(14.98,94.98)
  L08_SIG2 w0.094: v1(14.98,94.98) 15.35,95.35 16.04,95.35 17.05,96.36 19,96.36 23.33,92.03 23.33,89.49 v1(22.98,89.14)
  BOTTOM w0.107: U52.94 23.14,88.4 23.29,88.55 23.29,88.83 v1(22.98,89.14) ; U53.2 14.16,95.11 14.31,95.26 14.71,95.26 v1(14.98,94.98)
XDS_USB_ID: length 2.7
  BOTTOM w0.147: U52.95 22.74,85.63 22.47,85.36 R338.1
XDS_VREF: length 6.2
  TOP w0.147: v1(25.54,101.48) R354.2 C268.1 C267.1 U55.3
  BOTTOM w0.147: U52.9 v1(25.54,101.48)
XTAL_IN: length 12.1
  TOP w0.147: U1.T1 52.62,34.83 52.32,34.53 52.32,32.25 51.7,31.62 R178.2 50.85,30.95 48.81,28.91 47.05,28.91 46.59,29.37 R176.2
XTAL_OUT: length 4.5
  TOP w0.147: U1.R1 52.66,35.63 51.81,34.79 51.81,33.22 51.54,32.95 R179.2
N23200398: length 4.4
  BOTTOM w0.147: U52.96 22.34,85.91 21.24,84.81 C264.1 R339.1
N23200423: length 3.8
  BOTTOM w0.147: R345.1 R349.2 38.13,90.19 37.81,90.51 U52.60
N23200491: length 1.3
  TOP w0.147: R343.2 22.11,103.71 22.09,103.72 LD10.2
N23200507: length 6.3
  BOTTOM w0.147: R352.2 R348.1 37.31,85.8 37.33,85.82 37.33,89.14 37.16,89.31 U52.63
N23200509: length 5.3
  BOTTOM w0.147: U52.61 37.63,90.11 38.1,89.65 38.1,88.43 38.69,87.84 R346.1 R350.2
N23200516: length 7.2
  BOTTOM w0.147: U52.62 37.4,89.71 37.71,89.4 37.71,86.43 38.69,85.45 R351.2 R347.1
N23200616: length 0.8
  TOP w0.147: LD9.2 R342.1
N31943874: length 9.6
  TOP w0.147: R309.1 R306.1 38.55,75.5 39,75.04 R308.1 39.53,75.01 40.13,74.41 40.82,74.41 41.33,74.92 U46.8 v1(43.94,74.92)
  BOTTOM w0.147: v1(43.94,74.92) 43.96,74.94 R307.1
N32133653: length 1.9
  BOTTOM w0.147: U49.4 68.88,93.96 69.18,93.65 R329.2
N32133735: length 1.9
  TOP w0.147: SW6.5 R319.2
N32133737: length 1.9
  TOP w0.147: SW6.6 55.29,87.25 55.28,87.24 R318.2
N32133754: length 1.9
  TOP w0.147: SW6.7 R317.2
N32133756: length 1.9
  TOP w0.147: SW6.8 R316.2
N32302430: length 2.9
  TOP w0.147: SW10.4 52.69,105.84 52.7,105.85 R425.2 C336.1
N32359377: length 2.9
  TOP w0.147: SW12.4 66.61,106.37 R429.2 C338.1
N32360252: length 2.9
  TOP w0.147: C337.1 R426.2 59.69,104.83 SW11.4
N32781982: length 5.5
  BOTTOM w0.147: U26.9 40.52,67.66 39.86,68.33 R166.1 U26.12
N32800162: length 1.6
  TOP w0.147: R321.1 64.12,81.76 63.84,81.48 U47.16
N32800169: length 1.6
  TOP w0.147: U47.11 R320.1
N32801024: length 1.3
  TOP w0.147: LD11.2 R381.1
N32801040: length 1.3
  TOP w0.147: LD12.2 R382.1
N32801094: length 1.3
  TOP w0.147: LD13.2 R383.1
N32801104: length 1.3
  TOP w0.147: LD14.2 R384.1
N32801160: length 1.4
  TOP w0.147: LD15.2 R385.1
N32801170: length 1.4
  TOP w0.147: LD16.2 R386.1
N32801226: length 1.4
  TOP w0.147: LD17.2 R387.1
N32801236: length 1.4
  TOP w0.147: LD18.2 R388.1
N32801519: length 1.6
  BOTTOM w0.147: U59.9 R389.2
N32801526: length 1.6
  BOTTOM w0.147: U59.10 R390.2
N32801533: length 2.1
  BOTTOM w0.147: U59.7 70.99,69.96 71.26,69.69 R391.2
N32817219: length 4.4
  BOTTOM w0.147: U60.26 54.96,73.29 54.63,73.61 53.72,73.61 53.42,73.91 R393.2 R392.1
N32817226: length 1.9
  BOTTOM w0.147: R394.2 U60.28
N32843337: length 1.7
  TOP w0.147: SW1.2 R184.2
N32845049: length 20.3
  TOP w0.381: U41.6 26.56,35.19 26.57,35.2 C232.1 v1(27.94,35.2) C231.1 ; FL6.2 v1(20.37,47.55)
  L08_SIG2 w0.381: v1(27.94,35.2) 20.37,42.76 v1(20.37,47.55)
N32845083: length 3.5
  TOP w0.147: R273.2 R271.2 17.77,36.99 18.27,36.49 U41.1
N32845192: length 2.6
  TOP w0.147: U41.3 18.12,35.19 17.21,34.28 R272.1
N32845194: length 2.3
  TOP w0.147: R274.1 27.12,37.36 26.25,36.49 U41.8
N32845196: length 16.3
  TOP w0.147: U41.5 36.75,34.54 39.73,31.55 R275.1
N32845712: length 2.2
  TOP w0.147: U1.V9 R396.1
N32845714: length 4.2
  TOP w0.147: U1.T8 v1(58.58,34.43)
  BOTTOM w0.114: 58.98,33.2 58.98,34.03
  BOTTOM w0.147: 58.98,34.03 v1(58.58,34.43) ; R397.1 59.3,32.88 58.98,33.2
N32851242: length 2.2
  TOP w0.147: R331.1 J12.2
N32914108: length 2.5
  BOTTOM w0.147: R336.2 37.38,100.8 37.27,100.91 U52.34
N32995593: length 3.3
  TOP w0.147: R77.1 101.85,84.94 101.63,85.16 v1(101.04,85.16) R79.1
  BOTTOM w0.147: v1(101.04,85.16) 100.63,85.58 U14.4
N32995608: length 2.4
  BOTTOM w0.254: 98.31,86.05 99.01,86.76 99.12,86.76 99.12,86.75 99.89,86.75 99.89,86.76 U14.2
N32995634: length 1.6
  TOP w0.147: C95.1 v1(100.13,88.77)
  BOTTOM w0.147: U14.9 v1(100.13,88.77)
N33038314: length 1.1
  TOP w0.147: LD3.2 105.41,55.99 105.2,55.99 105.18,55.98 104.44,55.98 R48.2
N33056127: length 1
  TOP w0.147: LD6.2 R137.2
N33056129: length 1.5
  TOP w0.147: Q3.3 LD6.1
N33056157: length 2.6
  TOP w0.147: Q3.1 R146.1 R148.1
N33200463: length 3.2
  TOP w0.147: U1.A11 61.38,47.31 61.41,47.34 R139.2
N33200513: length 3.2
  TOP w0.147: R140.2 60.2,48.82 60.58,48.44 U1.A10
N33221101: length 3.3
  TOP w0.147: U1.U4 v1(55.38,33.63)
  BOTTOM w0.114: 55.78,32.57 55.78,33.23
  BOTTOM w0.147: 55.78,32.57 55.72,32.51 R400.1 ; 55.78,33.23 v1(55.38,33.63)
N33221125: length 3.4
  TOP w0.147: U1.U5 v1(56.18,33.63)
  BOTTOM w0.147: v1(56.18,33.63) 56.92,32.89 R398.1
N33221128: length 2.4
  TOP w0.147: U1.V3 54.86,33.11 54.86,31.44 R399.1
N33235493: length 1.4
  BOTTOM w0.147: R328.2 63.43,92.82 63.43,92.83 U50.4
N33277398: length 2.6
  TOP w0.147: Q4.1 R147.1 R149.1
N33277404: length 1
  TOP w0.147: LD7.2 R138.2
N33277419: length 1.5
  TOP w0.147: Q4.3 LD7.1
N33334993: length 1.9
  BOTTOM w0.147: R163.1 44.63,63.02 44.92,62.73 U27.2
N33461336: length 5.6
  TOP w0.147: R416.1 33.38,5.27 33.65,5 33.65,5 34.24,4.41 J15.43
N33514520: length 2.7
  BOTTOM w0.147: C247.1 R327.2 U50.2
N33770351: length 1.5
  TOP w0.147: R275.2 40.56,30.01 40.57,30.02 U43.2
N33879615: length 3.4
  TOP w0.147: U1.A9 59.78,48.28 58.99,49.07 R143.1
N33879618: length 4.2
  TOP w0.147: U1.B9 v1(59.38,46.43)
  BOTTOM w0.147: v1(59.38,46.43) 59.38,46.89 59.37,46.89 59.37,47.57 58.99,47.95 R145.1
N33879812: length 1.9
  TOP w0.147: U45.4 24.63,68.1 24.63,68.09 R283.2
N33879815: length 3.1
  TOP w0.147: U45.1 R282.2 R284.2
N33880944: length 5.9
  BOTTOM w0.147: U44.12 R281.1 36.55,71 35.82,71.73 U44.9
N33881371: length 17.1
  TOP w0.147: J10.2 12.91,68.1 14.07,66.93 C237.1 16.7,66.93 16.8,66.83 U45.6 20.35,66.83 20.7,67.17 20.7,69.84 21.61,70.75 SW5.1
N33882160: length 1.6
  TOP w0.147: R278.1 D6.1
N33883080: length 1.8
  TOP w0.147: R278.2 SW5.2
N33884757: length 2
  BOTTOM w0.147: U54.2 R344.2
N33885275: length 1.6
  BOTTOM w0.147: R199.2 31.66,72.93 U32.2
N33885316: length 1.7
  BOTTOM w0.147: U31.7 R197.2
N33885344: length 1.7
  BOTTOM w0.147: U31.6 R198.2
N33933588: length 1.8
  BOTTOM w0.147: R412.1 64.06,23.57 64.26,23.77 U74.9
N33933633: length 1.8
  BOTTOM w0.147: R413.1 65.45,23.43 65.26,23.61 U74.7
N33986982: length 4.5
  TOP w0.147: C235.1 D7.1 SW4.3
N34075368: length 1.7
  BOTTOM w0.147: U27.3 R163.2
N34422674: length 3.6
  TOP w0.147: R135.2 62.62,48.67 63.32,47.96 63.32,47.17 U1.A13
N34422702: length 4.3
  TOP w0.147: U1.B13 v1(63.38,46.43)
  BOTTOM w0.147: v1(63.38,46.43) 63.38,48.76 63.91,49.29 R136.2
N34549994: length 5.2
  TOP w0.147: U1.C9 v1(59.38,45.63)
  BOTTOM w0.147: v1(59.38,45.63) 60.07,46.32 60.07,48.25 60.25,48.43 R144.2
N34603287: length 3.6
  TOP w0.147: U1.N1 v1(52.83,37.23)
  BOTTOM w0.147: v1(52.83,37.23) 52.43,36.83 52.21,36.83 51.56,36.18 50.9,36.18 50.83,36.26 R90.2
N34603290: length 6.3
  TOP w0.147: U1.N4 v1(55.38,36.83)
  BOTTOM w0.114: 54.4,37.23 54.75,37.23
  BOTTOM w0.147: v1(55.38,36.83) 54.98,37.23 54.75,37.23 ; R91.2 50.83,37.4 51.17,37.75 53.04,37.75 53.65,37.14 54.05,37.14 54.14,37.23 54.4,37.23
N34603328: length 4.9
  TOP w0.147: R97.2 50.76,42.84 51.3,42.3 51.3,41.71 U1.K1
N34603356: length 4.8
  TOP w0.147: R87.2 50.2,38.23 50.82,37.62 51.56,37.62 52.37,36.81 53.22,36.81 53.22,36.82 53.77,36.82 U1.N2
N34603584: length 7.4
  TOP w0.147: U1.M4 v1(55.38,37.63)
  BOTTOM w0.114: 54.33,38.83 54.75,38.83 54.98,38.6 54.98,38.16
  BOTTOM w0.147: v1(55.38,37.63) 54.98,38.03 54.98,38.16 ; 54.33,38.83 54.12,38.83 54.04,38.75 52.91,38.75 50.83,40.83 R92.2
N34603591: length 5.6
  TOP w0.147: U1.P3 v1(54.58,36.03)
  BOTTOM w0.147: v1(54.58,36.03) 54.12,36.49 53.48,36.49 52.11,35.12 R93.2
N34660939: length 4.1
  BOTTOM w0.147: TP72.1 30.22,85.46 30.74,85.98 U52.75
N34662299: length 1.7
  BOTTOM w0.147: U56.6 R361.1
N34662301: length 1.7
  BOTTOM w0.147: U56.7 R362.1
N34663370: length 2.9
  BOTTOM w0.147: J11.27 58.24,101.25 56.88,99.9 R296.2
N34663404: length 2.7
  BOTTOM w0.147: J11.30 59.74,100.8 58.84,99.9 R298.2
N34663407: length 2.4
  BOTTOM w0.147: R299.2 60.07,100.57 60.24,100.74 J11.31
N34663410: length 2.4
  BOTTOM w0.147: J11.32 60.74,100.23 R300.2
N34663413: length 2.7
  BOTTOM w0.147: R297.2 57.85,99.9 58.74,100.79 J11.28
N34663434: length 2.7
  BOTTOM w0.147: R301.2 62.1,99.9 61.24,100.76 J11.33
N34665841: length 2.5
  BOTTOM w0.147: J11.36 62.74,100.77 63.11,100.39 R302.2
N34665844: length 2.7
  BOTTOM w0.147: R303.2 64.13,99.9 63.24,100.79 J11.37
N34665847: length 3.5
  BOTTOM w0.147: J11.38 63.74,100.8 63.97,100.57 65,100.57 65.15,100.42 R304.2
N34665853: length 4
  BOTTOM w0.147: J11.39 64.24,101.1 64.39,100.95 65.91,100.95 66.16,100.7 R305.2
N34666564: length 5.4
  TOP w0.147: R312.1 R309.2 41.06,77.2 41.32,77.46 U46.6 v1(43.94,77.46)
  BOTTOM w0.147: R310.1 v1(43.94,77.46)
N34666567: length 5.3
  TOP w0.147: R308.2 R313.1 41.14,76.06 41.27,76.19 U46.7 v1(43.94,76.19)
  BOTTOM w0.147: R311.1 44.01,76.26 v1(43.94,76.19)
N34733472: length 2.8
  TOP w0.147: TP13.1 109.67,35.54 109.67,35.58 108.69,36.55 U7.23
N34733475: length 3.2
  TOP w0.147: U7.26 108.69,45.92 108.69,45.92 108.69,46.23 108.69,46.23 108.69,46.32 109.02,46.65 109.67,46.65 TP15.1
N34733595: length 5.6
  TOP w0.147: U7.31 106.19,46.57 v1(105.66,47.1)
  BOTTOM w0.147: R32.2 105.87,44.94 105.24,45.57 105.24,46.68 v1(105.66,47.1)
N34755833: length 2.7
  TOP w0.305: v1(99.31,36.07) 99.19,36.18 U7.4 ; v1(98.67,36.07) 98.69,36.09 U7.3
N34755845: length 2.7
  TOP w0.305: v1(99.31,46.22) 99.19,46.1 U7.45 ; U7.46 98.69,46.2 v1(98.67,46.22)
N34755854: length 13.2
  TOP w0.147: v1(99.33,35.16) 99.76,35.59 99.76,36.25 99.69,36.33 U7.5
  L08_SIG2 w0.091: v1(99.33,35.16) 98.96,34.79 95.38,34.79 92.15,38.03 v1(90.77,38.03)
  BOTTOM w0.147: C55.2 v1(90.77,38.03)
N34755863: length 6.5
  TOP w0.147: v1(98.67,47.1) 99.18,47.1 99.76,46.52 99.76,46.03 99.69,45.96 U7.44
  BOTTOM w0.147: C56.2 96.01,47.01 96.44,47.44 98.34,47.44 v1(98.67,47.1)
N34755869: length 1.3
  BOTTOM w0.147: C55.1 92.85,38.78 R28.1
N34756880: length 8
  TOP w0.147: U7.19 v1(106.69,36.18)
  L03_SIG1 w0.091: v1(112.57,36.8) 111.95,36.18 v1(106.69,36.18)
  BOTTOM w0.147: v1(112.57,36.8) R36.1
N34775734: length 2.5
  TOP w0.147: C82.1 92.72,59.78 92.02,59.09 91.24,59.09 91.1,58.94 U9.8
N34778760: length 13.7
  L08_SIG2 w0.091: v1(92.58,72.93) 91.92,72.28 v1(91.92,64.14)
  BOTTOM w0.147: TP61.1 94.09,72.93 v1(92.58,72.93) 92.5,72.93 91.92,72.36 U35.48 ; U35.13 v1(91.92,64.14)
N34779936: length 1.4
  TOP w0.147: R222.2 111.88,55.66 111.63,55.91 Q7.1
N34780102: length 8
  TOP w0.147: R207.1 R211.1 72.08,37.22 71.58,36.72 70.12,36.72 68.07,38.77 67.04,38.77 U1.L18
N34780104: length 8.9
  TOP w0.147: U1.L17 66.58,38.43 67.99,38.43 70,36.42 71.6,36.42 72.08,35.95 R209.1 R208.1
N34780660: length 2.3
  BOTTOM w0.381: J7.2 100.38,63.39 100.44,63.32 FL3.2
N34780919: length 1.4
  BOTTOM w0.147: R223.2 112.93,58.5 Q8.1
N34780978: length 2.9
  BOTTOM w0.147: U35.29 84.98,67.84 84.26,67.12 84.26,66.78 83.67,66.19 R210.2
N34780980: length 1.9
  BOTTOM w0.147: R213.1 91.31,73.24 90.92,72.85 U35.46
N34780998: length 2.3
  BOTTOM w0.147: U35.32 84.25,69.34 83.67,69.93 R212.2
N34781014: length 1.4
  BOTTOM w0.147: Q6.1 R221.2
N34781978: length 0.9
  TOP w0.147: U15.3 R81.2
N34798910: length 1.2
  BOTTOM w0.147: C99.1 89.41,80.71 U16.4
N34800889: length 3.8
  TOP w0.147: U1.M1 51.55,38.03 50.2,39.38 R94.2
N34800892: length 6.4
  TOP w0.147: R95.2 50.76,41.7 50.96,41.51 50.96,40.78 51.09,40.64 51.27,40.64 51.47,40.84 51.65,40.84 51.78,40.71 51.78,40.53 51.58,40.33 51.58,40.15 51.71,40.02 51.9,40.02 52.1,40.22 52.28,40.22 52.41,40.09 52.41,39.91 52.21,39.71 52.21,39.52 52.9,38.83 U1.L1
N34800895: length 5.1
  TOP w0.147: R96.2 50.2,40.42 52.19,38.43 53.78,38.43 U1.L2
N34801624: length 5.3
  TOP w0.147: U1.K2 v1(53.78,39.23)
  BOTTOM w0.147: R191.1 50.26,42.03 53.06,39.23 v1(53.78,39.23)
N34801627: length 8.9
  TOP w0.147: U1.K4 v1(55.38,39.23)
  BOTTOM w0.147: R192.1 50.81,44.35 51.46,43.7 51.46,41.83 53.23,40.06 54.55,40.06 v1(55.38,39.23)
N34801682: length 8.7
  TOP w0.147: U1.J3 v1(54.58,40.83)
  BOTTOM w0.147: R193.1 50.91,45.5 51.76,44.65 51.76,42.02 53.36,40.41 54.17,40.41 v1(54.58,40.83)
N34801685: length 5.2
  TOP w0.147: R194.1 50.76,43.99 51.85,42.9 51.85,41.96 U1.J1
N34801688: length 12.8
  TOP w0.147: U1.J4 v1(55.38,40.83) ; v1(51.12,46.27) 51.12,47.06 50.76,47.42 R195.1
  L08_SIG2 w0.091: v1(55.38,40.83) 55.78,41.23 56.32,41.23 56.57,41.47 56.57,43.39 56.34,43.62 56.04,43.62 55.77,43.89 55.77,44.19 55.54,44.42 52.6,44.42 51.12,45.9 v1(51.12,46.27)
N34801691: length 6.9
  TOP w0.147: U1.K3 v1(54.58,39.23)
  BOTTOM w0.147: v1(54.58,39.23) 54.13,39.69 53.1,39.69 50.98,41.81 50.98,42.45 50.26,43.17 R196.1
N34820051: length 3.9
  BOTTOM w0.147: J11.26 57.74,101.21 57.48,100.95 56.13,100.95 55.88,100.7 R295.2
N34820524: length 2.3
  TOP w0.147: Q5.2 92.96,41.2 93.09,41.33 R200.2
N34820530: length 2
  TOP w0.147: LD8.2 Q5.3
N34828765: length 1.3
  TOP w0.147: R72.2 LD5.2
N34828799: length 2.2
  TOP w0.147: LD4.2 51.62,75.01 51.07,75.56 R73.2
N34828801: length 1.5
  TOP w0.147: LD4.1 Q2.3
N34828819: length 1.5
  TOP w0.147: Q2.1 54.96,78.83 55.22,79.09 R76.1
N34830317: length 3.2
  BOTTOM w0.147: R69.1 99.23,57.22 98.93,57.52 98.19,57.52 C92.1 97.72,57.62 U12.10
N34830329: length 5.1
  BOTTOM w0.147: C92.2 97.81,58.12 U12.9 ; C92.2 97.7,58.62 U12.8 ; C92.2 98.43,57.9 98.93,57.9 99.27,58.24 R71.1
N34830425: length 3.5
  BOTTOM w0.147: U13.10 87.09,53.58 87.06,53.55 C91.1 87.37,52.65 87.37,52.18 R68.1
